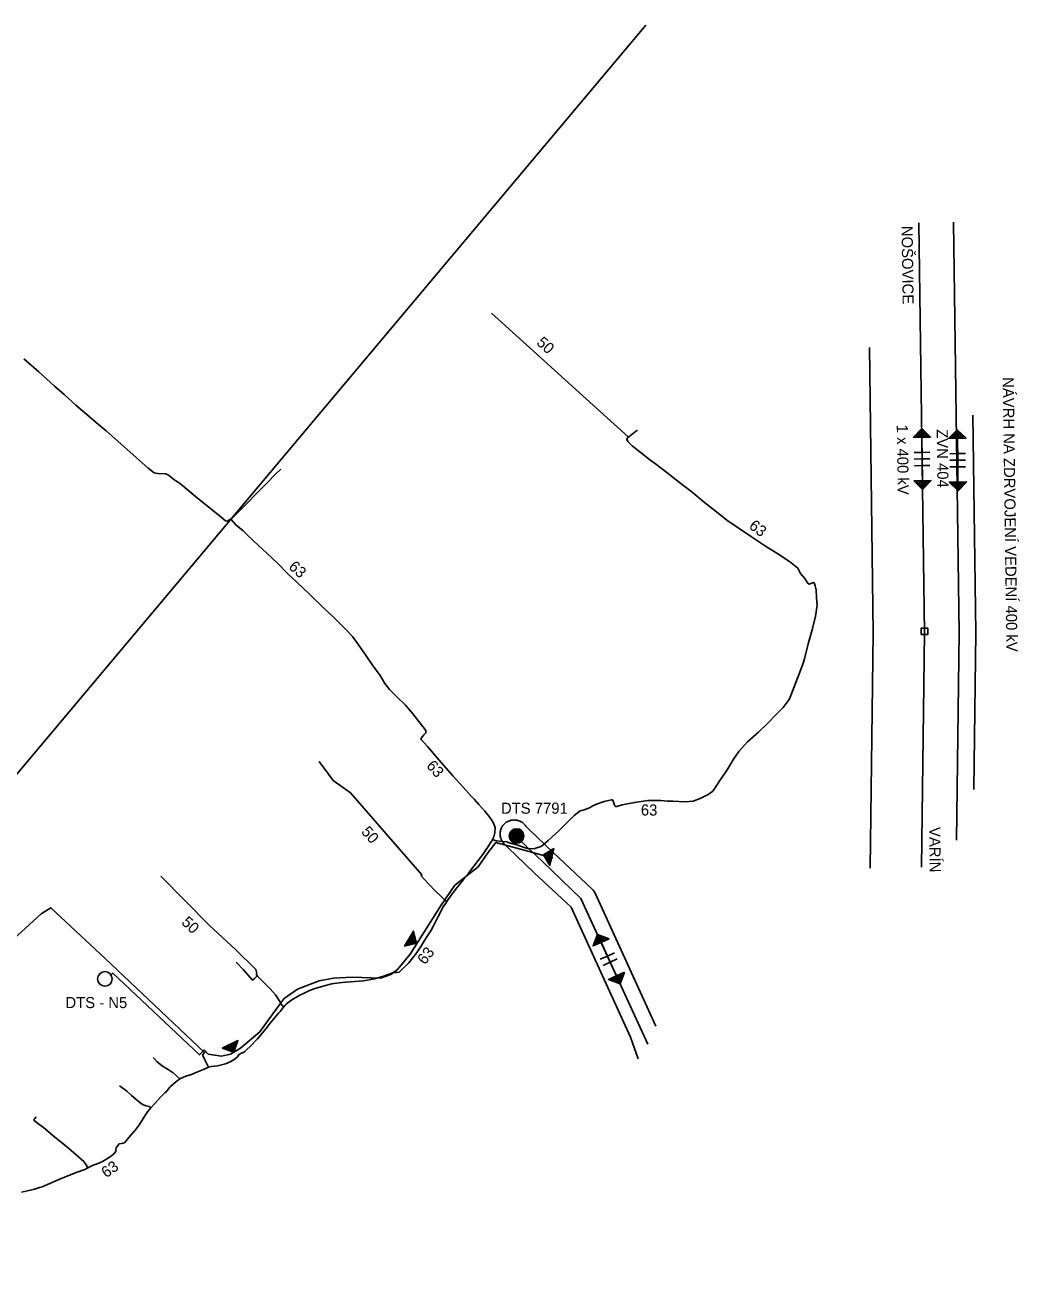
# Model space of a CAD drawing. Extents: x -444817 to -434929, y -1145681 to -1129851.
# Drawn here: x -441301 to -440585, y -1131975 to -1131064 of the extents above; entities that cross this region are included whole.
import ezdxf

# ---------------------------------------------------------------- set-up
doc = ezdxf.new("R2010")
doc.units = 0
for name, color, linetype in [('Vrstva 10', 7, 'Continuous'), ('Vrstva 11', 7, 'Continuous'), ('Vrstva 13', 7, 'Continuous'), ('Vrstva 15', 7, 'Continuous'), ('Vrstva 17', 7, 'Continuous'), ('Vrstva 18', 7, 'Continuous'), ('Vrstva 19', 7, 'Continuous'), ('Vrstva 21', 7, 'Continuous'), ('Vrstva 27', 7, 'Continuous'), ('Vrstva 30', 7, 'Continuous'), ('Vrstva 35', 7, 'Continuous'), ('Vrstva 38', 7, 'Continuous'), ('Vrstva 59', 7, 'Continuous'), ('Vrstva 9', 7, 'Continuous')]:
    doc.layers.add(name, color=color, linetype=linetype)

msp = doc.modelspace()

# ---------------------------------------------------------------- linework, layer by layer
at = {"layer": 'Vrstva 10'}
for p, q in [((-440881.78, -1131735.16), (-440886.88, -1131737.48)), ((-440876.69, -1131732.83), (-440881.78, -1131735.16)), ((-440879.8, -1131739.48), (-440884.9, -1131741.81)), ((-440874.71, -1131737.16), (-440879.8, -1131739.48))]:
    msp.add_line(p, q, dxfattribs=at)
for points in [[(-440948.79, -1131648.04), (-440928.47, -1131667.05), (-440900.84, -1131693.73), (-440852.55, -1131798.73)], [(-440886.32, -1131725.22), (-440880.79, -1131737.32), (-440875.27, -1131749.42)]]:
    msp.add_lwpolyline(points, dxfattribs=at)
for points in [[(-440880.59, -1131722.61), (-440892.05, -1131727.84), (-440888.94, -1131719.49)], [(-440882.42, -1131722.67), (-440890.8, -1131726.5), (-440888.53, -1131720.39)], [(-440884.24, -1131722.74), (-440889.56, -1131725.16), (-440888.11, -1131721.29)], [(-440886.07, -1131722.8), (-440888.31, -1131723.82), (-440887.7, -1131722.19)], [(-440869.54, -1131746.8), (-440872.65, -1131755.15), (-440881, -1131752.04)], [(-440870.78, -1131748.14), (-440873.06, -1131754.25), (-440879.17, -1131751.97)], [(-440872.03, -1131749.48), (-440873.47, -1131753.35), (-440877.34, -1131751.9)], [(-440873.28, -1131750.82), (-440873.88, -1131752.45), (-440875.51, -1131751.84)]]:
    msp.add_lwpolyline(points, close=True, dxfattribs=at)
at = {"layer": 'Vrstva 11'}
for radius in [5.25, 4.55, 3.85, 3.15, 2.45, 1.75, 1.05, 0.35]:
    msp.add_circle((-440947.2, -1131648.57), radius, dxfattribs=at)
at = {"layer": 'Vrstva 15'}
for points in [[(-440692.94, -1131296.37), (-440690.11, -1131502.12), (-440692.33, -1131671.75)], [(-440617.58, -1131614.95), (-440616.1, -1131502.09), (-440618.26, -1131345.26)], [(-440940.17, -1131641.97), (-440940.49, -1131641.45), (-440940.87, -1131640.92), (-440941.29, -1131640.41), (-440941.73, -1131639.94), (-440942.18, -1131639.52), (-440942.72, -1131639.07), (-440943.25, -1131638.69), (-440943.8, -1131638.35), (-440944.38, -1131638.04), (-440944.98, -1131637.77), (-440945.59, -1131637.54), (-440946.22, -1131637.35), (-440946.85, -1131637.2), (-440947.5, -1131637.09), (-440948.15, -1131637.03), (-440948.78, -1131637.01), (-440949.73, -1131637.03), (-440950.38, -1131637.09), (-440951.03, -1131637.2), (-440951.66, -1131637.35), (-440952.29, -1131637.54), (-440952.9, -1131637.77), (-440953.5, -1131638.04), (-440954.08, -1131638.35), (-440954.63, -1131638.69), (-440955.16, -1131639.07), (-440955.67, -1131639.49), (-440956.15, -1131639.94), (-440956.47, -1131640.28), (-440957.01, -1131640.92), (-440957.39, -1131641.45), (-440957.74, -1131642.01), (-440958.04, -1131642.58), (-440958.31, -1131643.18), (-440958.54, -1131643.79), (-440958.73, -1131644.42), (-440958.88, -1131645.06), (-440958.99, -1131645.7), (-440959.05, -1131646.35), (-440959.08, -1131646.99), (-440959.05, -1131647.77), (-440958.99, -1131648.42), (-440958.88, -1131649.07), (-440958.73, -1131649.7), (-440958.54, -1131650.33), (-440958.31, -1131650.94), (-440958.11, -1131651.39), (-440958.04, -1131651.54), (-440957.74, -1131652.11), (-440957.39, -1131652.67), (-440957.12, -1131653.08), (-440956.74, -1131653.61), (-440956.33, -1131654.12), (-440955.88, -1131654.6), (-440955.76, -1131654.71), (-440952.82, -1131657.56), (-440947.86, -1131662.36), (-440934.57, -1131675.22), (-440907.94, -1131699.92), (-440865.14, -1131793.63), (-440859.59, -1131809.14)], [(-440846.78, -1131785.71), (-440890.58, -1131689.8), (-440891.2, -1131688.64), (-440891.97, -1131687.58), (-440892.87, -1131686.62), (-440920.94, -1131660.58), (-440938.11, -1131643.96), (-440940.17, -1131641.97)]]:
    msp.add_lwpolyline(points, dxfattribs=at)
at = {"layer": 'Vrstva 17'}
msp.add_lwpolyline([(-440630.06, -1131651.58), (-440628.11, -1131502.1), (-440632.18, -1131206.12)], dxfattribs=at)
at = {"layer": 'Vrstva 18'}
msp.add_lwpolyline([(-441240.01, -1131749.2), (-441238.26, -1131747.45), (-441175.66, -1131806.42), (-441172.3, -1131802.77), (-441169.53, -1131805.83), (-441159.91, -1131807.29), (-441153.5, -1131805.83), (-441146.21, -1131801.6), (-441132.22, -1131789.8), (-441119.9, -1131772.52), (-441114.72, -1131765.75), (-441105.1, -1131759.04), (-441089.51, -1131753.06), (-441079.08, -1131750.95), (-441065.74, -1131750.44), (-441045.19, -1131751.17), (-441037.9, -1131748.4), (-441032.95, -1131744.9), (-441023.91, -1131733.68), (-441002.04, -1131699.13), (-440991.84, -1131684.11), (-440974.93, -1131670.7), (-440967.93, -1131660.79), (-440962.1, -1131653.21), (-440938.2, -1131659.63), (-440921.07, -1131664.65)], dxfattribs=at)
for points in [[(-440920.34, -1131657.54), (-440923.19, -1131669.82), (-440927.9, -1131662.26)], [(-440921.41, -1131659.03), (-440923.49, -1131668.01), (-440926.94, -1131662.48)], [(-440922.47, -1131660.52), (-440923.79, -1131666.21), (-440925.97, -1131662.7)], [(-440923.53, -1131662.01), (-440924.09, -1131664.4), (-440925.01, -1131662.93)], [(-441027.92, -1131727.95), (-441021.41, -1131717.16), (-441019.27, -1131725.81)], [(-441026.45, -1131726.86), (-441021.69, -1131718.97), (-441020.12, -1131725.3)], [(-441024.98, -1131725.78), (-441021.96, -1131720.78), (-441020.97, -1131724.79)], [(-441023.51, -1131724.69), (-441022.24, -1131722.59), (-441021.82, -1131724.28)], [(-441159.46, -1131801.53), (-441148.12, -1131796.03), (-441151.04, -1131804.45)], [(-441157.63, -1131801.42), (-441149.34, -1131797.39), (-441151.47, -1131803.55)], [(-441155.81, -1131801.31), (-441150.55, -1131798.76), (-441151.9, -1131802.66)], [(-441153.98, -1131801.2), (-441151.77, -1131800.13), (-441152.34, -1131801.77)]]:
    msp.add_lwpolyline(points, close=True, dxfattribs=at)
at = {"layer": 'Vrstva 19'}
msp.add_circle((-441243.99, -1131751.59), 5.25, dxfattribs=at)
at = {"layer": 'Vrstva 27'}
for points in [[(-441302.32, -1131304.54), (-441291.66, -1131313.89)], [(-441291.66, -1131313.89), (-441280.17, -1131324.28), (-441273.35, -1131330.22), (-441264.79, -1131337.87), (-441253.66, -1131347.51), (-441250, -1131350.63)], [(-441250, -1131350.63), (-441243.07, -1131356.55), (-441232.5, -1131365.87), (-441221.53, -1131375.61), (-441212.85, -1131383.34), (-441208.45, -1131386.85), (-441205.9, -1131387.26), (-441199.98, -1131387.43), (-441198.18, -1131388.32), (-441193.4, -1131392.26), (-441191.1, -1131393.44), (-441187.98, -1131395.87), (-441178.69, -1131403.9), (-441168.92, -1131411.77), (-441160.09, -1131418.73), (-441156.93, -1131421.31), (-441155.76, -1131421.57), (-441154.72, -1131420.97), (-441153.88, -1131420.39), (-441153.4, -1131420.22)], [(-440734.19, -1131500), (-440734.17, -1131499.94), (-440731.85, -1131490.01), (-440730.67, -1131482.24), (-440731, -1131476.75), (-440731.26, -1131471.13), (-440732.11, -1131468.09), (-440732.67, -1131466.07), (-440733.01, -1131465.78), (-440733.29, -1131465.73), (-440736.41, -1131466.94), (-440736.74, -1131466.87), (-440737.15, -1131466.45), (-440738.01, -1131465.26), (-440738.28, -1131464.95), (-440739.53, -1131463.02), (-440742.46, -1131459.36), (-440744.56, -1131455.4), (-440750.55, -1131450.74), (-440758.88, -1131445.03), (-440767.75, -1131439.72), (-440777.92, -1131432.84), (-440786.75, -1131426.83), (-440795.64, -1131420.77), (-440803.1, -1131414.95), (-440811.7, -1131408.14), (-440820.7, -1131400.63), (-440829.77, -1131393.74), (-440838.85, -1131386.59), (-440847.1, -1131380.3), (-440850.1, -1131377.96), (-440857.21, -1131372.58), (-440863.95, -1131367.2), (-440867.14, -1131364.23), (-440867.72, -1131362.53), (-440866.7, -1131360.69)], [(-440860.17, -1131356.08), (-440861.52, -1131357), (-440866.28, -1131360.8), (-440867.09, -1131361.39)], [(-441153.4, -1131420.22), (-441152.29, -1131419.36), (-441150.33, -1131417.47), (-441141.24, -1131408.38), (-441135.09, -1131402.23), (-441127.75, -1131394.7), (-441120.91, -1131387.67), (-441117.17, -1131383.97)], [(-441070.07, -1131500), (-441072.1, -1131497.84), (-441079.4, -1131490.47), (-441085.86, -1131484.44), (-441096.58, -1131474.12), (-441105.52, -1131465.46), (-441112.2, -1131459.56), (-441119.53, -1131451.89), (-441127.19, -1131444.62), (-441136.54, -1131435.94), (-441141.11, -1131431.57), (-441144.33, -1131428.63), (-441149.5, -1131424.16), (-441152.91, -1131420.45), (-441153.4, -1131420.22)], [(-440980.05, -1131619.85), (-440985.79, -1131613.32), (-440993.11, -1131605.08), (-441003.09, -1131593.79), (-441011.45, -1131584.1), (-441015.9, -1131578.99), (-441016.15, -1131578.3), (-441016.1, -1131577.93), (-441014.05, -1131575.74), (-441012.59, -1131574.19), (-441012.57, -1131573.47), (-441012.72, -1131572.41), (-441016.79, -1131567.33), (-441022.87, -1131559.34), (-441027.27, -1131554.29), (-441033.52, -1131548.22), (-441038.78, -1131542.84), (-441042.1, -1131538.7), (-441045.64, -1131532.83), (-441049.64, -1131527.32), (-441050.97, -1131525.3), (-441055.73, -1131518.7), (-441059.92, -1131512.47), (-441065.56, -1131504.81), (-441070.07, -1131500)], [(-440924.34, -1131651.81), (-440916.75, -1131644.88), (-440911.2, -1131639.3), (-440905.77, -1131633.67), (-440901.46, -1131630.43), (-440898.46, -1131629.66), (-440894.65, -1131628.29), (-440892.3, -1131626.92), (-440889.56, -1131625.63), (-440884.1, -1131623.73), (-440878.69, -1131622.39), (-440878.1, -1131622.39), (-440877.88, -1131622.66), (-440876.71, -1131626.32), (-440876.33, -1131626.75), (-440875.66, -1131627.22), (-440874.94, -1131627.22), (-440871.04, -1131626.2), (-440862.11, -1131624.35), (-440852.53, -1131622.95), (-440843.3, -1131623), (-440838.38, -1131623.48), (-440834.57, -1131623.54), (-440826.06, -1131623.95), (-440820.03, -1131623.55), (-440814.97, -1131621.6), (-440809.18, -1131618.53), (-440805.71, -1131616.19), (-440802.36, -1131611.25), (-440800.74, -1131608.52), (-440796.85, -1131603.06), (-440795.42, -1131600.87), (-440790.92, -1131593.16), (-440786.95, -1131587.63), (-440780.72, -1131580.74), (-440772.89, -1131573.68), (-440765.58, -1131566.77), (-440761.07, -1131561.96), (-440755.17, -1131555.96), (-440750.85, -1131550.12), (-440749.48, -1131547.32), (-440745.9, -1131537.81), (-440743.01, -1131530.54), (-440740.73, -1131524.02), (-440739.63, -1131520.88), (-440736.93, -1131510.07), (-440734.19, -1131500)], [(-440964.63, -1131651.04), (-440963.72, -1131649.12), (-440962.86, -1131646.19), (-440962.64, -1131642.43), (-440963.28, -1131640.47), (-440964.23, -1131638.23), (-440967.02, -1131634.58), (-440970.21, -1131630.72), (-440974.33, -1131625.8), (-440977.91, -1131622.07), (-440980.05, -1131619.85)], [(-441210.73, -1131844.53), (-441207.65, -1131841.26), (-441203.87, -1131836.74), (-441200.83, -1131833.8), (-441199.24, -1131832.47), (-441198.06, -1131830.93), (-441197.08, -1131829.71), (-441196.62, -1131829.14), (-441193.1, -1131825.93), (-441189.87, -1131823.58), (-441185.67, -1131821.78), (-441181.45, -1131820.46), (-441178.95, -1131819.41), (-441172.98, -1131816.85), (-441169.19, -1131815.26), (-441167.18, -1131814.77), (-441162.77, -1131814.25), (-441157.01, -1131812.9), (-441153.19, -1131811.26), (-441150.34, -1131809.56), (-441148.35, -1131807.66), (-441147.46, -1131806.29), (-441146.24, -1131805.37), (-441144.8, -1131804.82), (-441143.31, -1131804.25), (-441142.52, -1131803.57), (-441138.35, -1131799.35), (-441135.18, -1131796), (-441134.07, -1131794.74), (-441131.4, -1131791.71), (-441128, -1131787.58), (-441124.74, -1131783.58), (-441123.56, -1131782.08), (-441121.3, -1131779.15), (-441118.8, -1131776.19), (-441117.57, -1131775.08), (-441116.76, -1131773.88), (-441115.18, -1131772.02), (-441113.91, -1131770.51), (-441112.95, -1131769.57), (-441109.22, -1131766.69), (-441103.94, -1131763.55), (-441099.96, -1131761.58), (-441097.42, -1131760.36), (-441096.57, -1131759.96), (-441092.51, -1131758.61), (-441086.55, -1131756.78), (-441085.98, -1131756.61), (-441080.47, -1131755.1), (-441074.98, -1131754.49), (-441070.41, -1131753.99), (-441060.83, -1131753.29), (-441057.65, -1131753.06), (-441049.63, -1131751.45), (-441043.06, -1131749.74), (-441038.37, -1131747.97), (-441036.24, -1131747.02), (-441033.66, -1131746.86), (-441033.5, -1131746.9), (-441031.74, -1131746.83), (-441024.8, -1131739.89), (-441019.64, -1131733.17), (-441015.85, -1131727.48), (-441013.61, -1131723.93), (-441012.41, -1131722.03), (-441009.14, -1131716.84), (-441007.14, -1131713.22), (-441003.88, -1131707.01), (-441000.17, -1131699.7), (-440997.81, -1131696.28), (-440997.52, -1131695.86), (-440994.43, -1131691.31), (-440991.22, -1131687.04), (-440985.36, -1131679.83), (-440983.41, -1131677.42), (-440982.7, -1131676.54), (-440981.14, -1131674.3), (-440974.92, -1131666.11), (-440971.54, -1131661.98), (-440968.19, -1131656.8), (-440965.11, -1131652.06), (-440964.63, -1131651.04)], [(-440964.63, -1131651.04), (-440964.35, -1131651.24), (-440961.6, -1131652.16), (-440957.51, -1131652.63), (-440954.2, -1131652.84), (-440952.54, -1131653.61), (-440946.21, -1131655.08), (-440941.82, -1131656.8), (-440938.59, -1131657.79), (-440933.96, -1131657.52), (-440929.7, -1131656.16), (-440928.29, -1131655.06), (-440926.3, -1131653.52), (-440924.34, -1131651.81)], [(-440997.52, -1131695.86), (-440999.29, -1131694.55), (-441001.92, -1131692.05), (-441005.62, -1131688.41), (-441010.16, -1131683.47), (-441013.86, -1131679.64), (-441015.82, -1131677.54), (-441015.83, -1131677.38), (-441015.67, -1131676.92), (-441015.33, -1131676.51)], [(-441149.25, -1131739.76), (-441148.94, -1131739.94), (-441144.38, -1131744.77), (-441137.53, -1131752.41), (-441136.15, -1131751.38), (-441134.18, -1131749.33)], [(-441115.18, -1131772.02), (-441116.69, -1131769.94), (-441117.44, -1131768.6), (-441121.03, -1131763.04), (-441124.79, -1131758.84), (-441130.49, -1131753.09), (-441133.82, -1131749.83), (-441134.69, -1131748.62), (-441134.75, -1131747.92), (-441134.53, -1131747.64)], [(-441033.66, -1131746.86), (-441033.49, -1131746.69)], [(-441169.17, -1131815.25), (-441172.27, -1131809.51), (-441173.48, -1131806.75), (-441173.32, -1131806.02), (-441172.32, -1131804.89), (-441171.74, -1131804.36)], [(-441209.2, -1131808.24), (-441208.53, -1131808.98), (-441206.35, -1131811.3), (-441202.34, -1131814.49), (-441198.43, -1131817.02), (-441194.73, -1131819.27), (-441189.87, -1131823.58)], [(-441210.73, -1131844.53), (-441210.88, -1131844.45), (-441212.01, -1131843.57), (-441214.53, -1131843.02), (-441216.19, -1131842.47), (-441217.15, -1131842), (-441218.87, -1131840.77), (-441221.67, -1131838.36), (-441224.68, -1131835.75), (-441228.2, -1131832.44), (-441229.61, -1131831.35), (-441230.52, -1131830.81), (-441232.07, -1131829.75), (-441233.39, -1131828.74)], [(-441279.99, -1131865.68), (-441288.24, -1131858.74), (-441291.55, -1131856.42), (-441295.03, -1131853.64), (-441295.07, -1131852.99), (-441294.42, -1131852.12), (-441293.49, -1131851.06)], [(-441250, -1131885.19), (-441245.6, -1131883.27), (-441240.07, -1131879.87), (-441237.67, -1131878.03), (-441236.15, -1131876.07), (-441236.02, -1131874.27), (-441235.86, -1131873.3), (-441234.73, -1131871.76), (-441233.68, -1131870.59), (-441232.1, -1131870.29), (-441230.75, -1131870.03), (-441229.65, -1131869.59), (-441226.6, -1131865.82), (-441221.92, -1131860.38), (-441219.05, -1131856.56), (-441215.19, -1131850.39), (-441213.15, -1131847.38), (-441210.73, -1131844.53)], [(-441256.36, -1131887.88), (-441257.5, -1131885.58), (-441259.13, -1131883.28), (-441264.76, -1131878.35), (-441271.96, -1131872.29), (-441279.99, -1131865.68)], [(-441304, -1131905.38), (-441299.7, -1131904.32), (-441294.74, -1131903.09), (-441291.2, -1131902.06), (-441289.07, -1131901.39), (-441283.58, -1131899.04), (-441277.2, -1131896.27), (-441264.78, -1131891.22), (-441258.49, -1131888.94), (-441256.36, -1131887.88)], [(-441256.36, -1131887.88), (-441252.41, -1131885.91), (-441250.2, -1131885.28), (-441250, -1131885.19)]]:
    msp.add_lwpolyline(points, dxfattribs=at)
at = {"layer": 'Vrstva 35'}
msp.add_line((-440866.7, -1131360.69), (-440965.19, -1131271.64), dxfattribs=at)
for points in [[(-441015.52, -1131676.67), (-441067.04, -1131617.45), (-441079.48, -1131608.57), (-441089.54, -1131594.95)], [(-441134.53, -1131747.64), (-441135.14, -1131744.84), (-441149.5, -1131730.63), (-441168.74, -1131712.86), (-441203.68, -1131677.48)], [(-441172.15, -1131804.57), (-441243.8, -1131736.77), (-441282.88, -1131700.35), (-441289.98, -1131704.79), (-441343.57, -1131753.35), (-441364.89, -1131784.14), (-441413.15, -1131746.84), (-441443.07, -1131726.61), (-441450.65, -1131717.86)]]:
    msp.add_lwpolyline(points, dxfattribs=at)
at = {"layer": 'Vrstva 59'}
msp.add_lwpolyline([(-440854.12, -1131064.05), (-441457.58, -1131782.51), (-441240.62, -1132136.45)], dxfattribs=at)
at = {"layer": 'Vrstva 9'}
for p, q in [((-440660.58, -1131372.06), (-440654.98, -1131371.99)), ((-440660.52, -1131376.82), (-440654.92, -1131376.75)), ((-440654.98, -1131371.99), (-440649.38, -1131371.91)), ((-440654.92, -1131376.75), (-440649.32, -1131376.67)), ((-440629.35, -1131372.85), (-440634.95, -1131372.93)), ((-440629.28, -1131377.61), (-440634.88, -1131377.69)), ((-440623.75, -1131372.77), (-440629.35, -1131372.85)), ((-440623.68, -1131377.53), (-440629.28, -1131377.61)), ((-440660.45, -1131381.58), (-440654.85, -1131381.51)), ((-440654.85, -1131381.51), (-440649.25, -1131381.43)), ((-440629.22, -1131382.37), (-440634.82, -1131382.45)), ((-440623.62, -1131382.29), (-440629.22, -1131382.37))]:
    msp.add_line(p, q, dxfattribs=at)
for points in [[(-440655.32, -1131670.99), (-440653.11, -1131502.1), (-440657.18, -1131206.47)], [(-440654.7, -1131392.42), (-440654.92, -1131376.75), (-440655.13, -1131361.07)], [(-440629.5, -1131361.93), (-440629.28, -1131377.61), (-440629.07, -1131393.29)]]:
    msp.add_lwpolyline(points, dxfattribs=at)
for points in [[(-440661.43, -1131361.15), (-440655.22, -1131354.77), (-440648.83, -1131360.98)], [(-440659.75, -1131360.43), (-440655.2, -1131355.76), (-440650.53, -1131360.3)], [(-440658.07, -1131359.71), (-440655.19, -1131356.75), (-440652.23, -1131359.63)], [(-440656.39, -1131358.98), (-440655.18, -1131357.74), (-440653.93, -1131358.95)], [(-440623.2, -1131361.84), (-440635.8, -1131362.02), (-440629.59, -1131355.63)], [(-440624.9, -1131361.17), (-440634.12, -1131361.29), (-440629.57, -1131356.62)], [(-440626.6, -1131360.49), (-440632.44, -1131360.57), (-440629.56, -1131357.61)], [(-440628.3, -1131359.81), (-440630.76, -1131359.85), (-440629.54, -1131358.6)], [(-440661, -1131392.51), (-440648.4, -1131392.34), (-440654.61, -1131398.72)], [(-440659.3, -1131393.19), (-440650.08, -1131393.06), (-440654.63, -1131397.73)], [(-440657.6, -1131393.86), (-440651.76, -1131393.78), (-440654.64, -1131396.74)], [(-440655.9, -1131394.54), (-440653.44, -1131394.51), (-440654.65, -1131395.75)], [(-440622.77, -1131393.2), (-440628.98, -1131399.59), (-440635.37, -1131393.37)], [(-440624.45, -1131393.92), (-440628.99, -1131398.6), (-440633.67, -1131394.05)], [(-440626.13, -1131394.65), (-440629.01, -1131397.61), (-440631.97, -1131394.73)], [(-440627.81, -1131395.37), (-440629.02, -1131396.62), (-440630.27, -1131395.4)], [(-440655.52, -1131503.39), (-440650.79, -1131503.39), (-440650.79, -1131498.66), (-440655.52, -1131498.66)]]:
    msp.add_lwpolyline(points, close=True, dxfattribs=at)

# ---------------------------------------------------------------- texts
at = {"layer": 'Vrstva 13'}
for s, p in [('NOŠOVICE', (-440669.73, -1131208.73)), ('NÁVRH NA ZDRVOJENÍ VEDENÍ 400 kV', (-440596.86, -1131317.82)), ('1 x 400 kV', (-440673.18, -1131352.06)), ('ZVN 404', (-440644.44, -1131355.33)), ('VARÍN', (-440649.83, -1131642.15))]:
    msp.add_text(s, height=8, rotation=270.78892, dxfattribs=at).set_placement(p)
msp.add_text('DTS 7791', height=8, dxfattribs=at).set_placement((-440958.48, -1131632.51))
at = {"layer": 'Vrstva 21'}
msp.add_text('DTS - N5', height=8, dxfattribs=at).set_placement((-441272.41, -1131772.64))
at = {"layer": 'Vrstva 30'}
for rotation, p in [(322.77798, (-440780.33, -1131426.23)), (318.54798, (-441112.09, -1131455.32)), (311.47566, (-441012.72, -1131598.24)), (359.68963, (-440857.66, -1131633.78)), (52.48625, (-441013.2, -1131741.88)), (35.55505, (-441242.97, -1131895.41))]:
    msp.add_text('63', height=8, rotation=rotation, dxfattribs=at).set_placement(p)
at = {"layer": 'Vrstva 38'}
for rotation, p in [(317.88038, (-440933.39, -1131293.65)), (311.02327, (-441059.64, -1131645.77)), (316.73294, (-441189.29, -1131711.52))]:
    msp.add_text('50', height=8, rotation=rotation, dxfattribs=at).set_placement(p)

doc.saveas('drawing.dxf')
